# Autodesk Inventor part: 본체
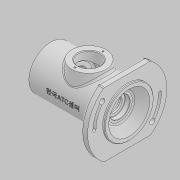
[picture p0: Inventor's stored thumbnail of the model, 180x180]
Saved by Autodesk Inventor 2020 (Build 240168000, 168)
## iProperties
Created: 2022-05
Part Number: 본체
Material: 일반
Document SubType Name: Modeling
Designer: User
Density: 1 g/cm^3
Appearance: 기본값
Author: User
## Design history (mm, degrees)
sketch "스케치1"
  geometry: L1 (-57.5, 0)-(-57.5, 32); L2 (-57.5, 32)-(44.5, 32); L3 (44.5, 32)-(44.5, 58); L4 (44.5, 58)-(54.5, 58); L5 (54.5, 58)-(54.5, 36); L6 (54.5, 36)-(57.5, 36); L7 (57.5, 36)-(57.5, 0); L8 (57.5, 0)-(-57.5, 0); L9 (-49.5, 0)-(-49.5, 24); L10 (-49.5, 24)-(-46.5, 24); L11 (-46.5, 24)-(-46.5, 22.5); L12 (-46.5, 22.5)-(-35.5, 22.5); L13 (-35.5, 22.5)-(-35.5, 17.5); L14 (-35.5, 17.5)-(-33.25, 17.5); L15 (-33.25, 17.5)-(-33.25, 18.5); L16 (-33.25, 18.5)-(-31.5, 18.5); L17 (-31.5, 18.5)-(-31.5, 17.5); L18 (-31.5, 17.5)-(-20.5, 17.5); L19 (-20.5, 17.5)-(-20.5, 27); L20 (-20.5, 27)-(17.5, 27); L21 (17.5, 27)-(17.5, 17.5); L22 (17.5, 17.5)-(28.5, 17.5); L23 (28.5, 17.5)-(28.5, 15); L24 (28.5, 15)-(33.5, 15); L25 (33.5, 15)-(33.5, 11); L26 (33.5, 11)-(36.2, 11); L27 (36.2, 11)-(36.2, 15); L28 (36.2, 15)-(43.5, 15); L29 (43.5, 15)-(43.5, 20); L30 (43.5, 20)-(57.5, 30); 2 further points
  constraints: 60 end point, 24 perpendicular, 6 point on line, 1 coincident, 1 horizontal, 1 midpoint, 1 parallel, 1 vertical
  dimensions: "d0" = 115 distance of L7.end L1.start; "d1" = 3 distance of L5.end L6.end; "d2" = 10 distance of L3.end L4.end; "d3" = 64 diameter of L2 L8; "d4" = 72 diameter of L6 L8; "d5" = 116 diameter of L4 L8; "d6" = 48 diameter of L10 L8; "d7" = 45 diameter of L12 L8; "d8" = 35 diameter of L14 L8; "d9" = 37 diameter of L16 L8; "d10" = 54 diameter of L20 L8; "d12" = 30 diameter of L24 L8; "d13" = 22 diameter of L26 L8; "d14" = 30 diameter of L28 L8; "d15" = 40 diameter of L29.end L8; "d16" = 60 diameter of L30.end L8; "d17" = 14 distance between parallel lines of L7 L29; "d18" = 29 distance between parallel lines of L7 L23; "d19" = 5 distance of L23.end L24.end; "d20" = 7.3 distance of L27.end L28.end; "d21" = 11 distance between parallel lines of L21 L23; "d22" = 11 distance between parallel lines of L19 L17; "d23" = 38 distance of L19.end L20.end; "d24" = 3 distance of L9.end L10.end; "d25" = 22 distance between parallel lines of L1 L13; "d26" = 8 distance between parallel lines of L1 L9; "d27" = 1.75 distance of L15.end L16.end
revolve "회전1" sketch "스케치1" stored, may be unused: angle "d28" = 90 deg
sketch "스케치2"
  geometry: L1 (-33.985, 47)-(33.985, 47); L2 (-33.985, -47)-(33.985, -47); A1 r 58 centre (0, 0) between (-33.985, 47) and (33.985, 47) reference; 1 further point
  constraints: 4 end point, 4 point on circle, 1 horizontal, 1 parallel
  dimensions: "d29" = 94 distance between parallel lines of L2 L1; "d30" = 47 distance from line of point (0, 0) L1
extrude "돌출1" cut sketch "스케치2" extent not by distance; stored distance "d31" = 0; taper "d32" = 0 deg
sketch "스케치3"
  geometry: L1 (0, 0)-(36.77, 30.854); L2 (0, 0)-(-36.77, -30.854); L3 (-48, 0)-(48, 0); A1 r 48 centre (0, 0) between (48, 0) and (36.77, 30.854); A2 r 52 centre (0, 0) between (52, 0) and (39.834, 33.425); A3 r 44 centre (0, 0) between (44, 0) and (33.706, 28.283); A4 r 4 centre (48, 0) between (44, 0) and (52, 0); A5 r 4 centre (36.77, 30.854) between (39.834, 33.425) and (33.706, 28.283); A6 r 48 centre (0, 0) between (-48, 0) and (-36.77, -30.854); A7 r 52 centre (0, 0) between (-52, 0) and (-39.834, -33.425); A8 r 44 centre (0, 0) between (-44, 0) and (-33.706, -28.283); A9 r 4 centre (-48, 0) between (-44, 0) and (-52, 0); A10 r 4 centre (-36.77, -30.854) between (-39.834, -33.425) and (-33.706, -28.283); A11 r 45.75 centre (0, 0) between (-45.75, 0) and (-35.047, -29.408); A12 r 2.25 centre (-48, 0) between (-45.75, 0) and (-50.25, 0); A13 r 50.25 centre (0, 0) between (-50.25, 0) and (-38.494, -32.3); A14 r 2.25 centre (-36.77, -30.854) between (-38.494, -32.3) and (-35.047, -29.408); A15 r 45.75 centre (0, 0) between (45.75, 0) and (35.047, 29.408); A16 r 2.25 centre (48, 0) between (45.75, 0) and (50.25, 0); A17 r 50.25 centre (0, 0) between (50.25, 0) and (38.494, 32.3); A18 r 2.25 centre (36.77, 30.854) between (38.494, 32.3) and (35.047, 29.408); 1 further point
  constraints: 36 point on circle, 18 centre point, 8 tangent, 6 end point, 2 coincident, 2 horizontal alignment, 1 horizontal, 6 other
  dimensions: "d33" = 48 radius of A6; "d34" = 48 radius of A1; "d35" = 4 radius of A5; "d36" = 4 radius of A9; "d37" = 40 deg angle of L3 L1; "d38" = 40 deg angle of L3 L2; "d41" = 4.5 radial gap between concentric circles of A13 A11; "d42" = 4.5 radial gap between concentric circles of A17 A15
extrude "돌출2" cut sketch "스케치3" distance "d39" = 4.4; taper "d40" = 0 deg
extrude "돌출3" cut sketch "스케치3" extent not by distance; stored distance "d43" = 102; taper "d44" = 0 deg
sketch "스케치4"
  geometry: L1 (-58, 0)-(58, 0); L2 (-52.193, -43.795)-(52.193, 43.795); A1 r 58 centre (0, 0) between (-33.985, 47) and (-33.985, -47) reference; A2 r 58 centre (0, 0) between (33.985, -47) and (33.985, 47) reference; A3 r 48 centre (0, 0) between (-36.77, -30.854) and (36.77, 30.854); 2 further points
  constraints: 4 end point, 4 point on circle, 2 midpoint, 2 point on line, 1 centre point, 1 coincident
  dimensions: "d45" = 40 deg angle of L1 L2; "d46" = 96 diameter of A3
hole "구멍1" sketch "스케치4" at (-36.77, -30.854), (36.77, 30.854) diameter "d47" = 8; stored, may be unused: countersink angle "d51" = 60 deg, drill point angle "d53" = 118 deg; dims "d48" = 6, "d49" = 4.25, "d50" = 2, "d52" = 6
sketch "스케치5"
  geometry: C1 r 32 at (0, 0) reference; 2 further points
  constraints: 1 coincident
hole "구멍2" sketch "스케치5" at (0, 0) diameter "d54" = 43.376; stored, may be unused: countersink angle "d58" = 60 deg, drill point angle "d60" = 0 deg; dims "d55" = 90, "d56" = 4.25, "d57" = 2, "d59" = 8
node "작업 평면1"
sketch "스케치6"
  geometry: L1 (57.5, 32)-(57.5, -32) reference; C1 r 25 at (1.5, 0); 1 further point
  constraints: 1 centre point, 1 horizontal alignment
  dimensions: "d62" = 50 diameter of C1; "d63" = 56 distance from line of C1.centre L1
extrude "돌출4" join sketch "스케치6" stored distance "d64" = 4.4; taper "d65" = 5 deg
sketch "스케치7"
  geometry: C1 r 25 at (0, 0) reference; 2 further points
  constraints: 1 coincident
hole "구멍3" sketch "스케치7" at (0, 0) diameter "d66" = 32; stored, may be unused: countersink angle "d70" = 60 deg, drill point angle "d72" = 0 deg; dims "d67" = 90, "d68" = 4.25, "d69" = 2, "d71" = 20
fillet "모깎기1" dims "d73" = 3
fillet "모깎기2" dims "d74" = 0.6, "d75" = 0.5
chamfer "모따기1" distance "d76" = 1; stored, may be unused: second distance "d77" = 2, angle "d78" = 45 deg
chamfer "모따기2" distance "d79" = 1; stored, may be unused: second distance "d80" = 2, angle "d81" = 45 deg
chamfer "모따기3" distance "d82" = 0.7; stored, may be unused: second distance "d83" = 2, angle "d84" = 30 deg
sketch "스케치8" dims "d85" = 41
  geometry: L1 (0, 0)-(0, 20.5); C1 r 16 at (0, 0) reference; 2 further points
  constraints: 2 coincident, 2 end point, 1 vertical, 1 vertical alignment, 2 other
hole "구멍4" sketch "스케치8" at (0, 20.5) diameter "d86" = 2.62111; stored, may be unused: countersink angle "d90" = 60 deg, drill point angle "d92" = 118 deg; dims "d87" = 6, "d88" = 4.25, "d89" = 2, "d91" = 8
chamfer "모따기4" distance "d96" = 1; stored, may be unused: second distance "d97" = 2, angle "d98" = 30 deg
node "작업 평면2"
sketch "스케치9"
  geometry: L1 (61, -47)-(61, 47) reference; 2 further points
  constraints: 1 horizontal alignment, 1 other
  dimensions: "d99" = 62 distance from line of L1 point (-1, 0)
feature "엠보싱1" sketch "스케치9" dims "d0" = 115, "d1" = 3, "d2" = 10, "d3" = 64, "d4" = 72, "d5" = 116, "d6" = 48, "d7" = 45, "d8" = 35, "d9" = 37, "d10" = 54, "d12" = 30, "d13" = 22, "d14" = 30, "d15" = 40, "d16" = 60, "d17" = 14, "d18" = 29, "d19" = 5, "d20" = 7.3, "d21" = 11, "d22" = 11, "d23" = 38, "d24" = 3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
chamfer "모따기5" distance "d102" = 1; stored, may be unused: second distance "d103" = 2, angle "d104" = 30 deg
fillet "모깎기3" dims "d105" = 3
fillet "모깎기4" dims "d106" = 3
node "솔리드1"
pattern_circular "원형 패턴1" dims angle "d94" = 360 deg
feature "A9D066F2-1C7D-4E18-AEED-F7BC21143FA4" dims "d47" = 8, "d48" = 6, "d49" = 4.25, "d50" = 2, "d51" = 60 deg, "d52" = 6, "d53" = 118 deg
other parameters: "d61" = 38
